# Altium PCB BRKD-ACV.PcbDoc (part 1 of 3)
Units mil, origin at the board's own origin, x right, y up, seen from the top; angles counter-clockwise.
Board outline 5708.66 x 3740.16 mil, 4 copper layers (L1-TOP, L2-GND, L3-PWR, L4-BOT), stack 61.722 mil thick; 171 components, 263 nets, 918 pads, 406 vias.
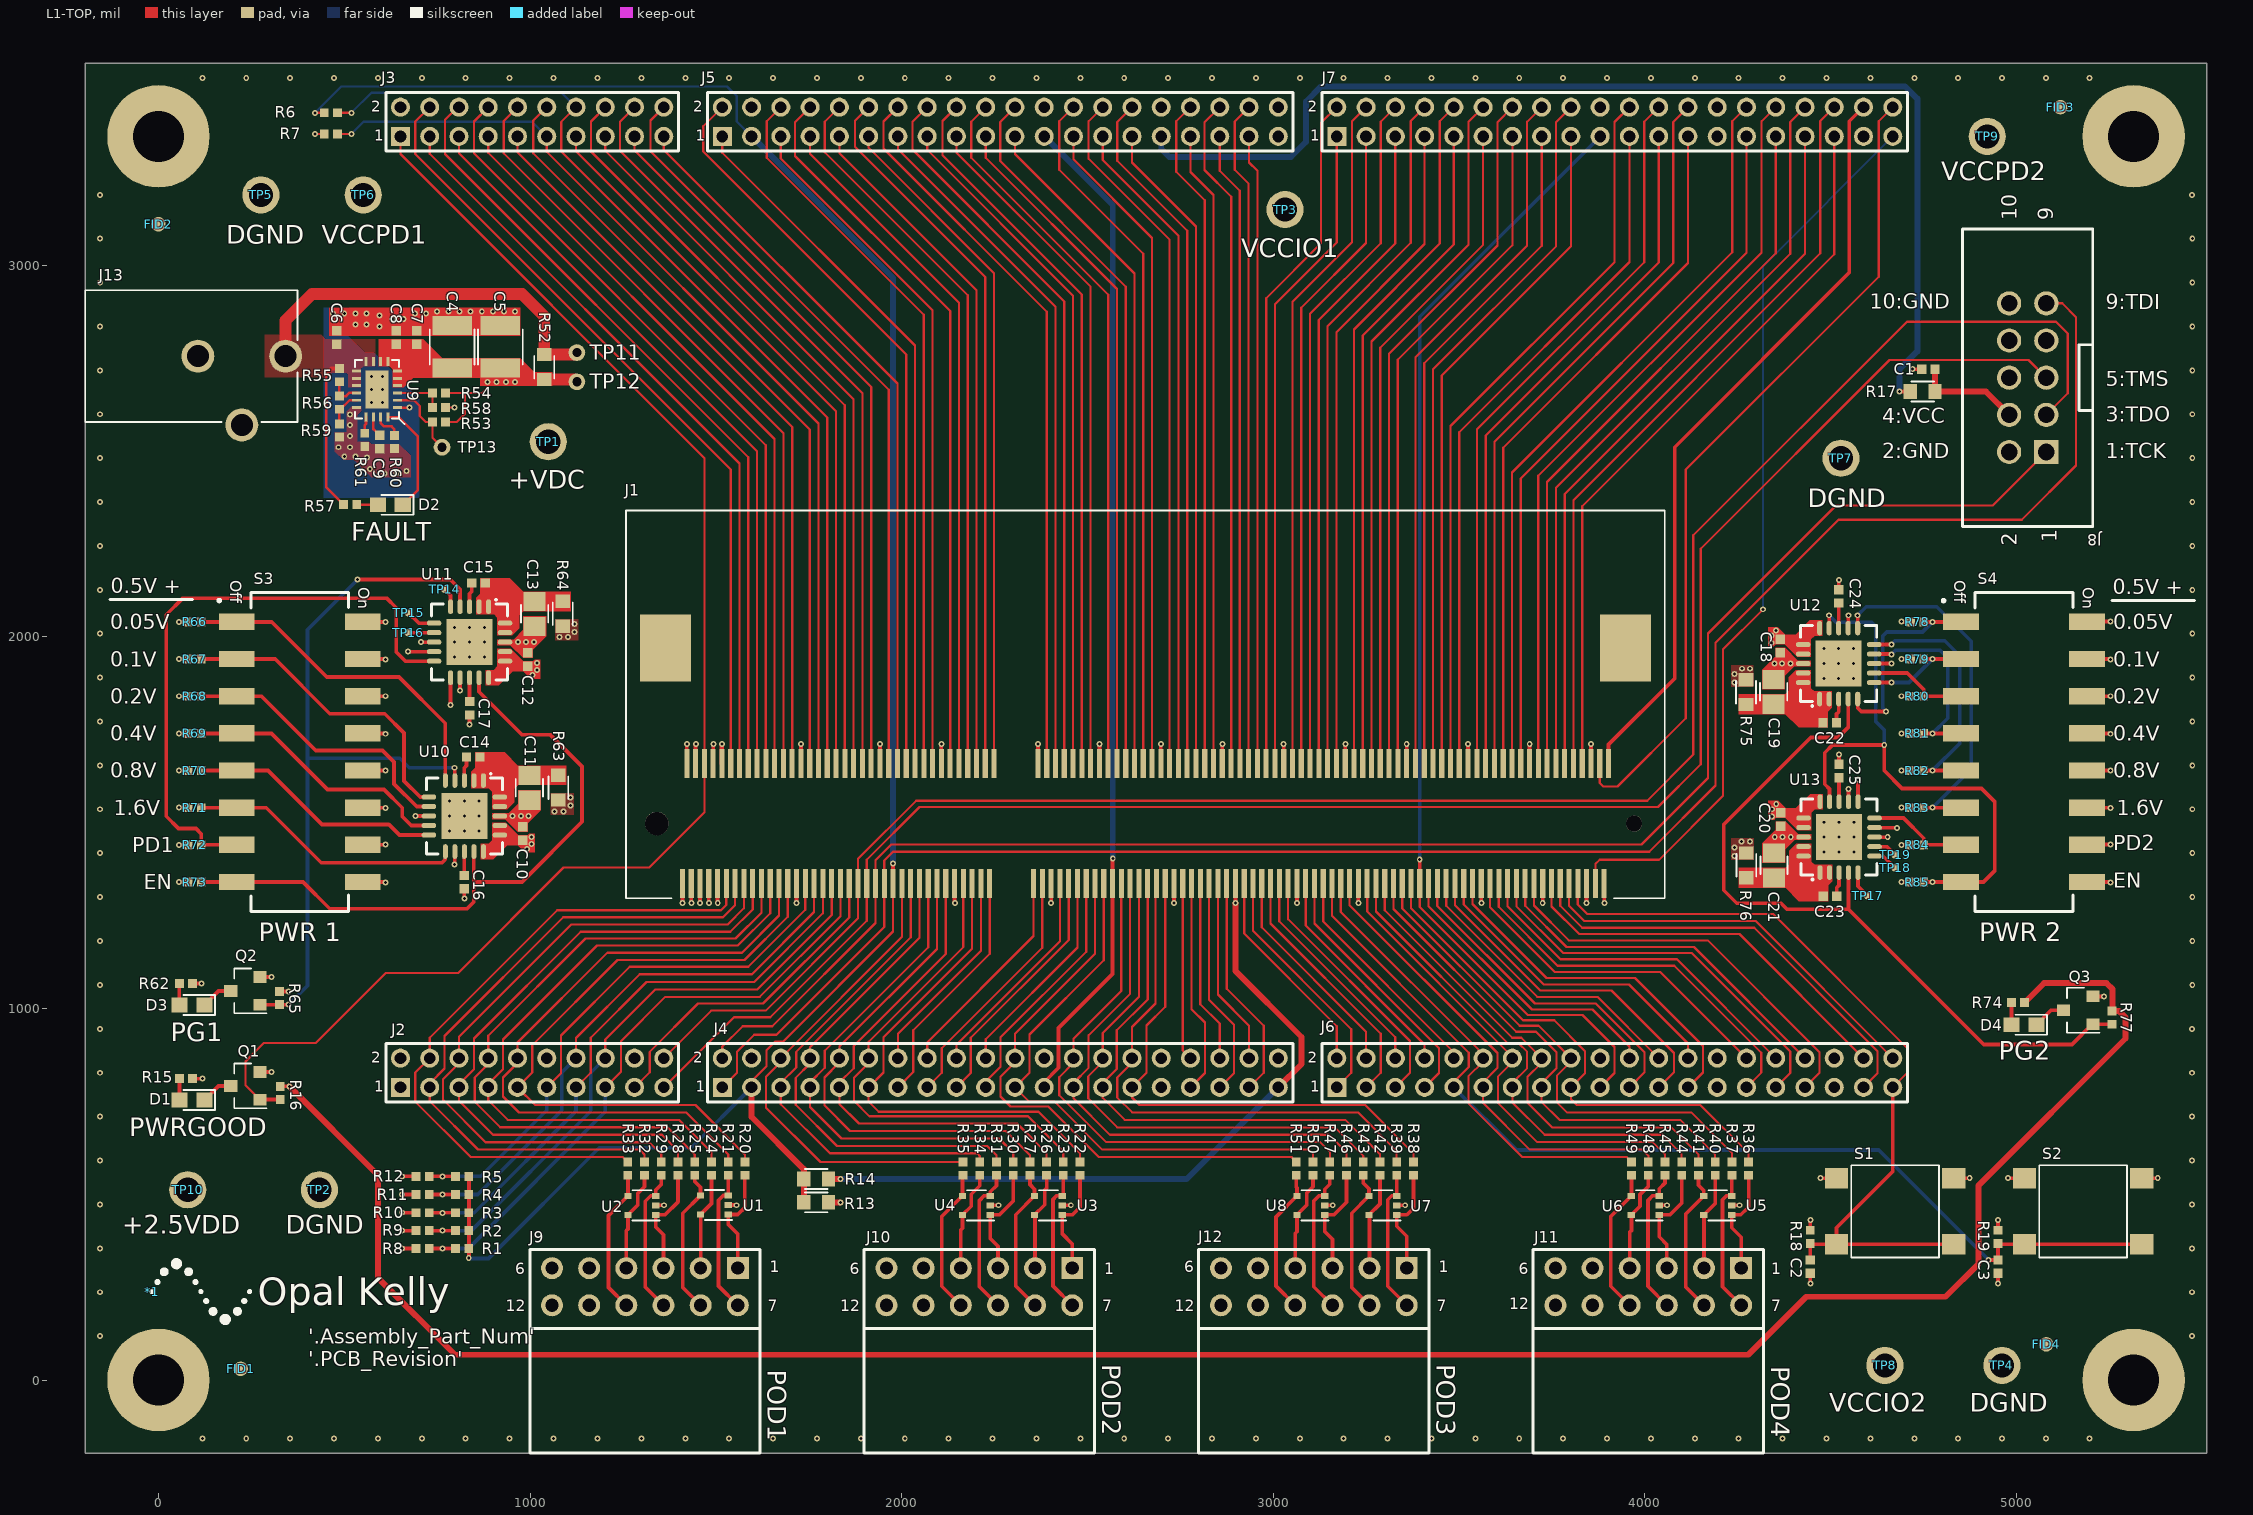
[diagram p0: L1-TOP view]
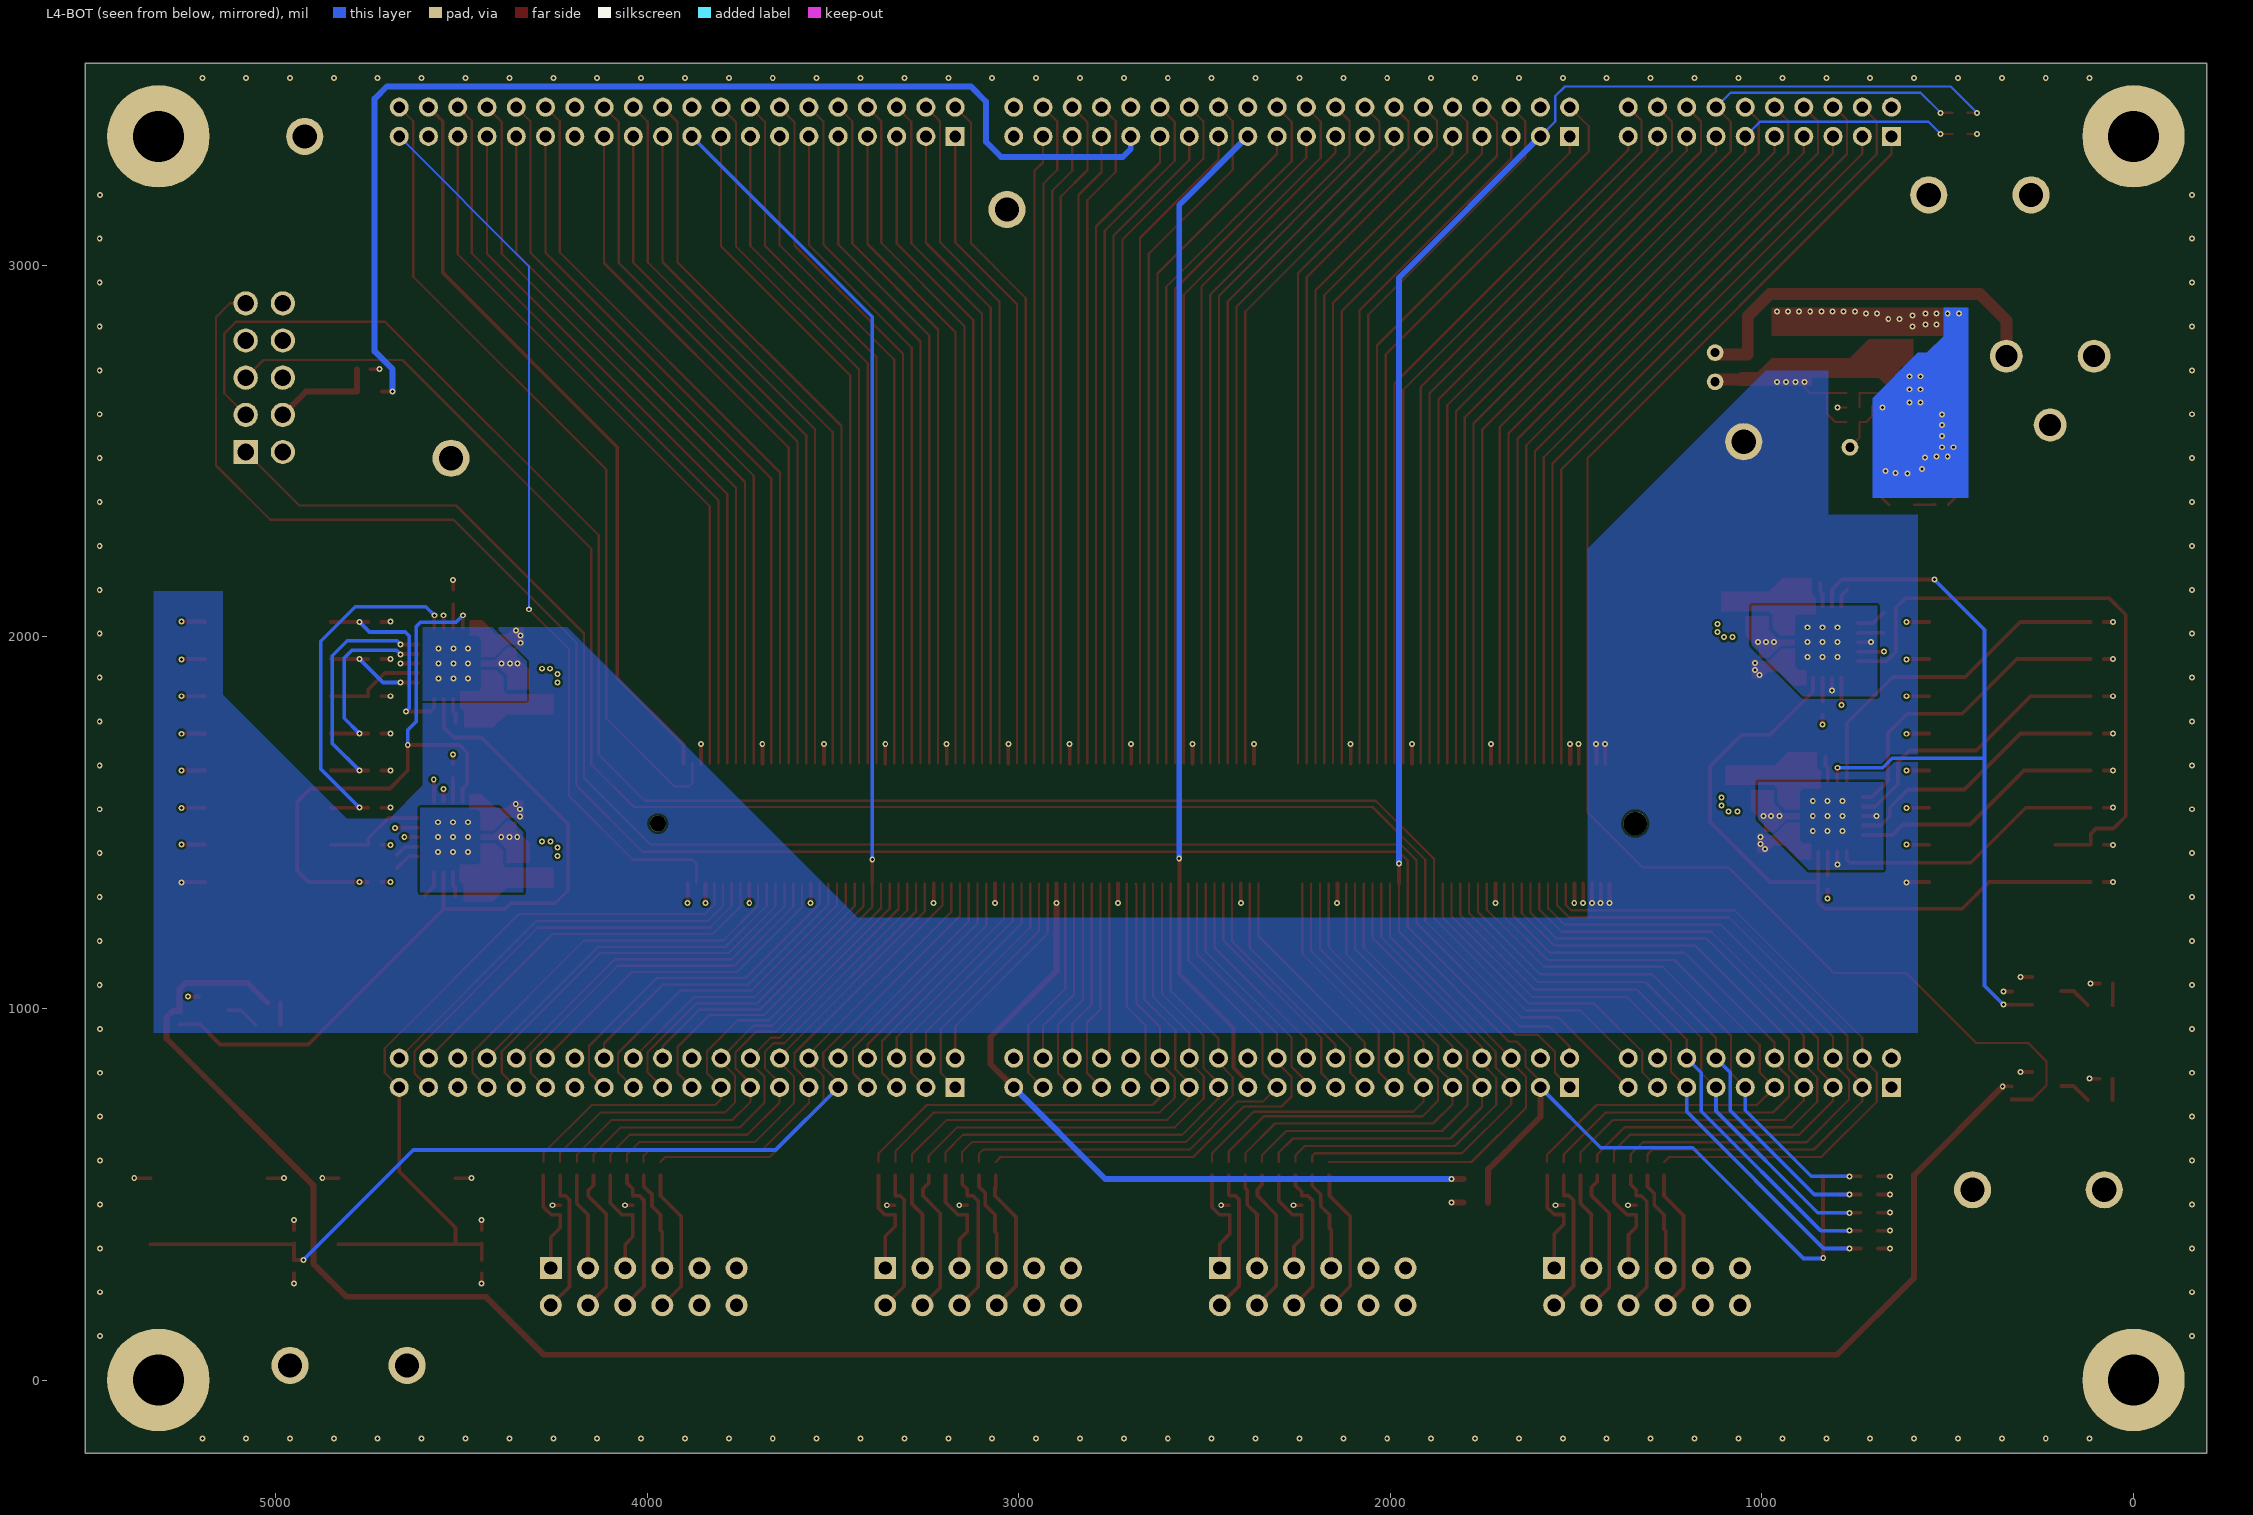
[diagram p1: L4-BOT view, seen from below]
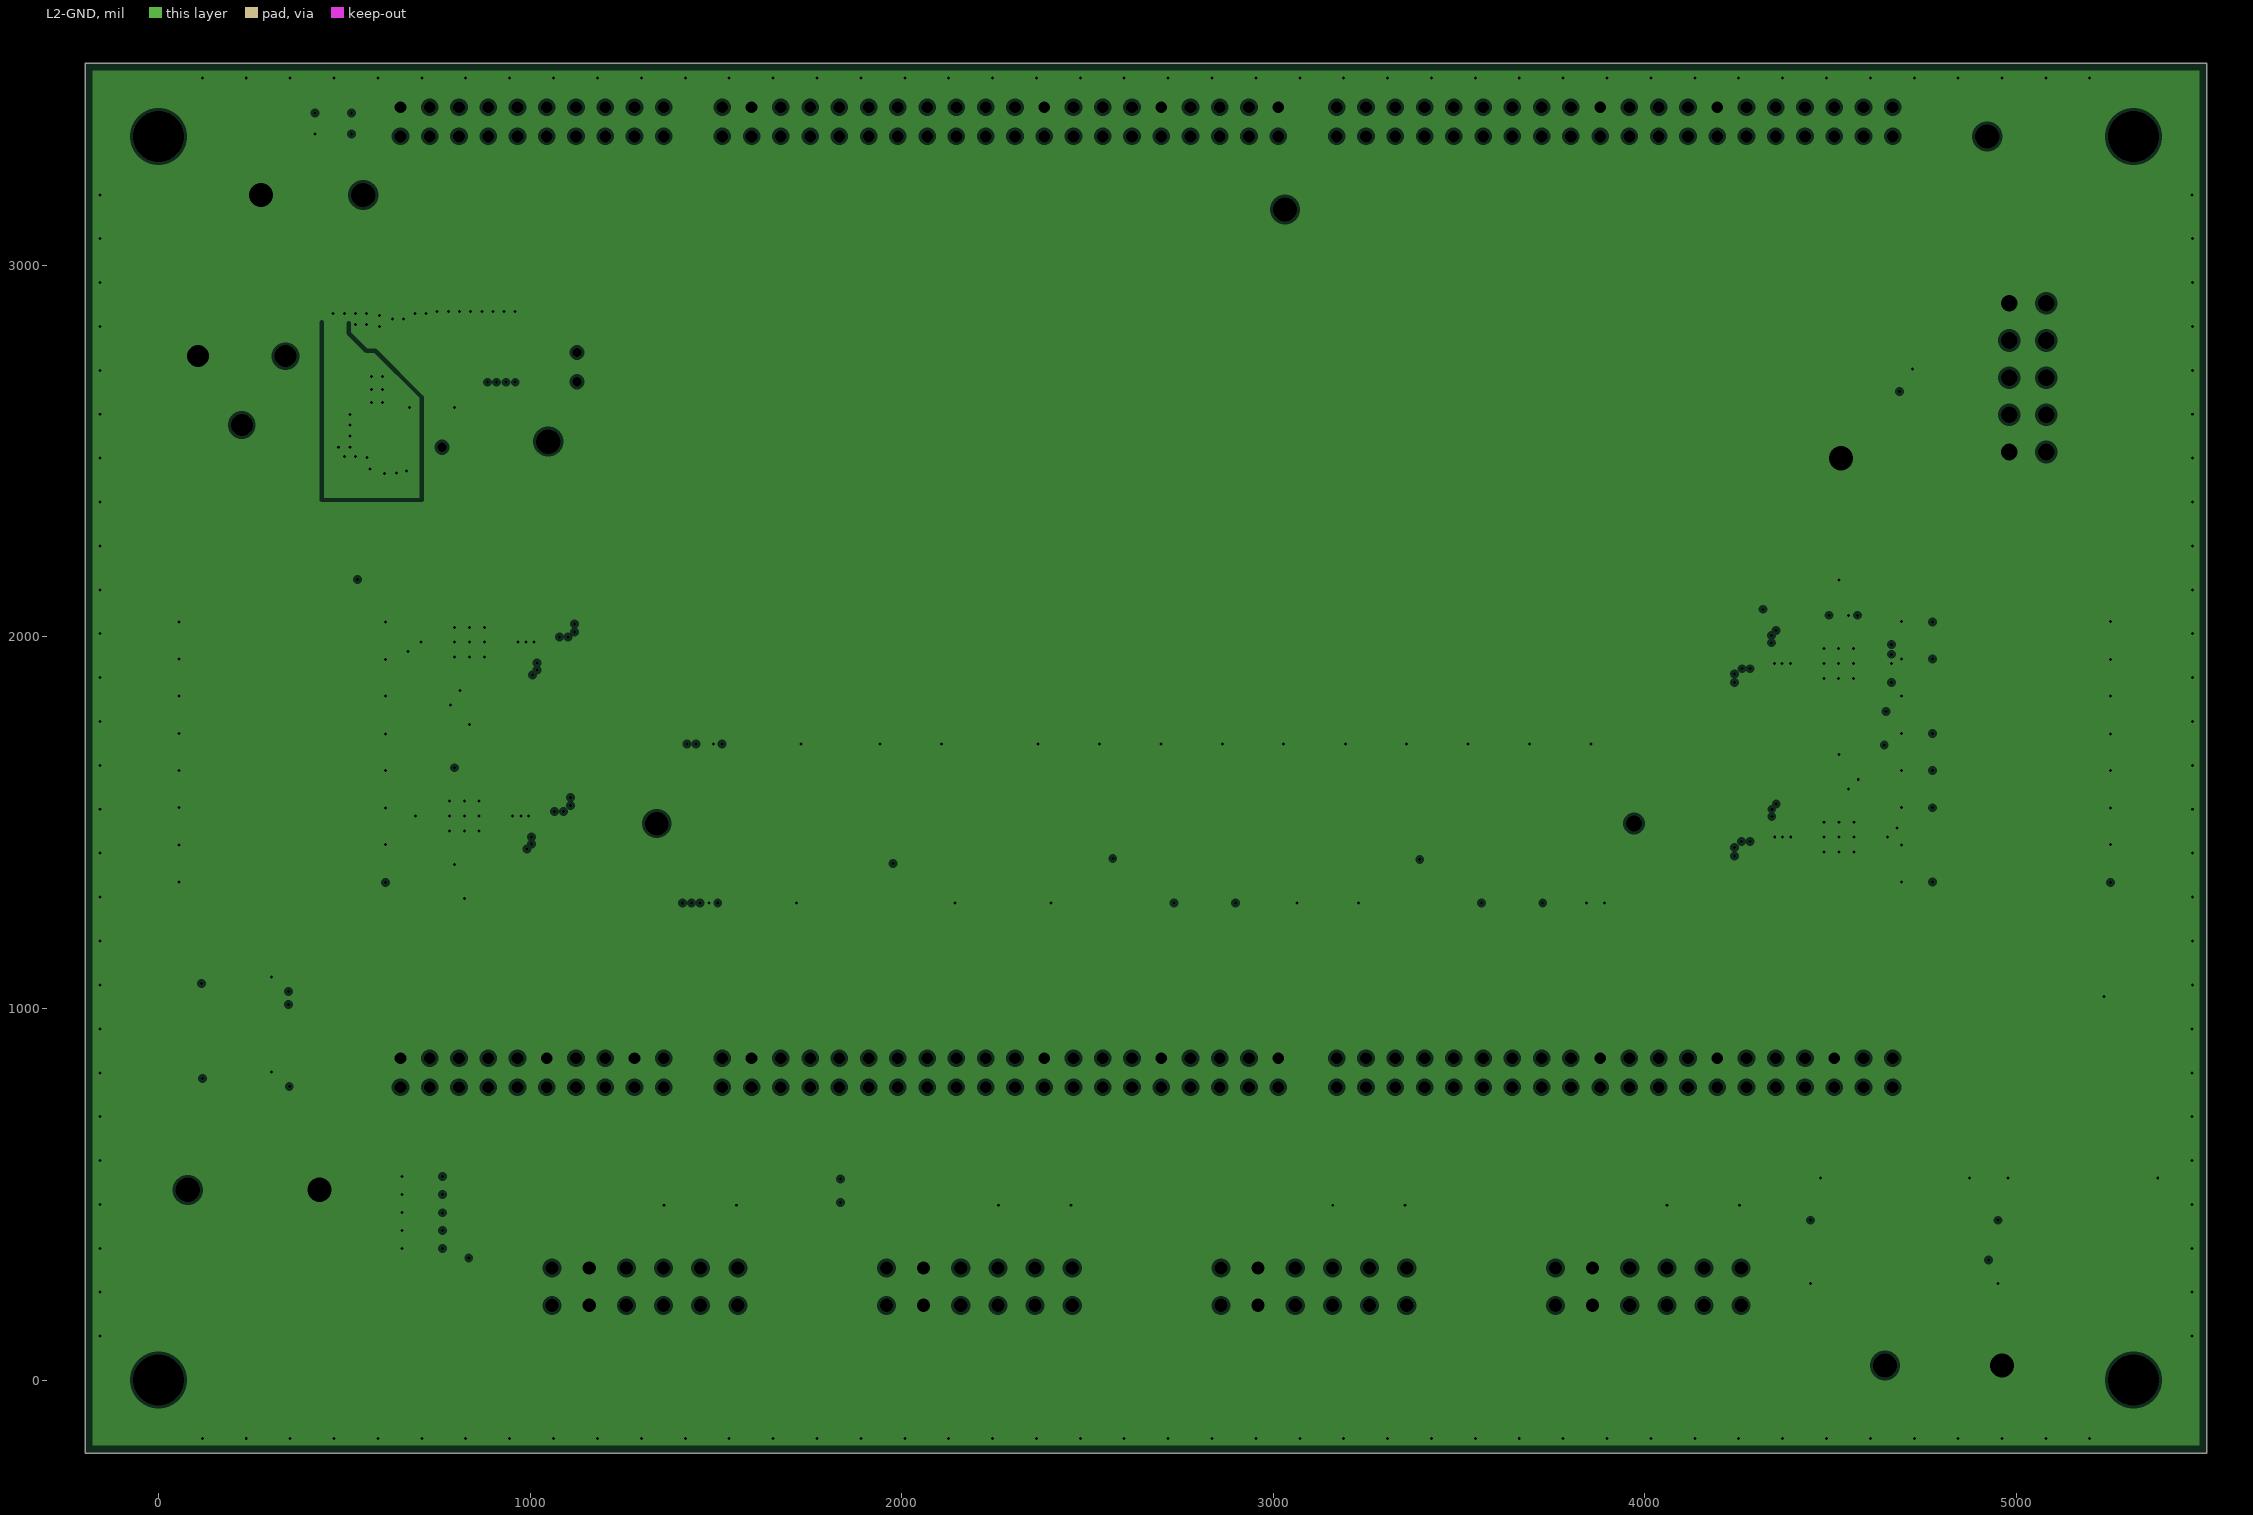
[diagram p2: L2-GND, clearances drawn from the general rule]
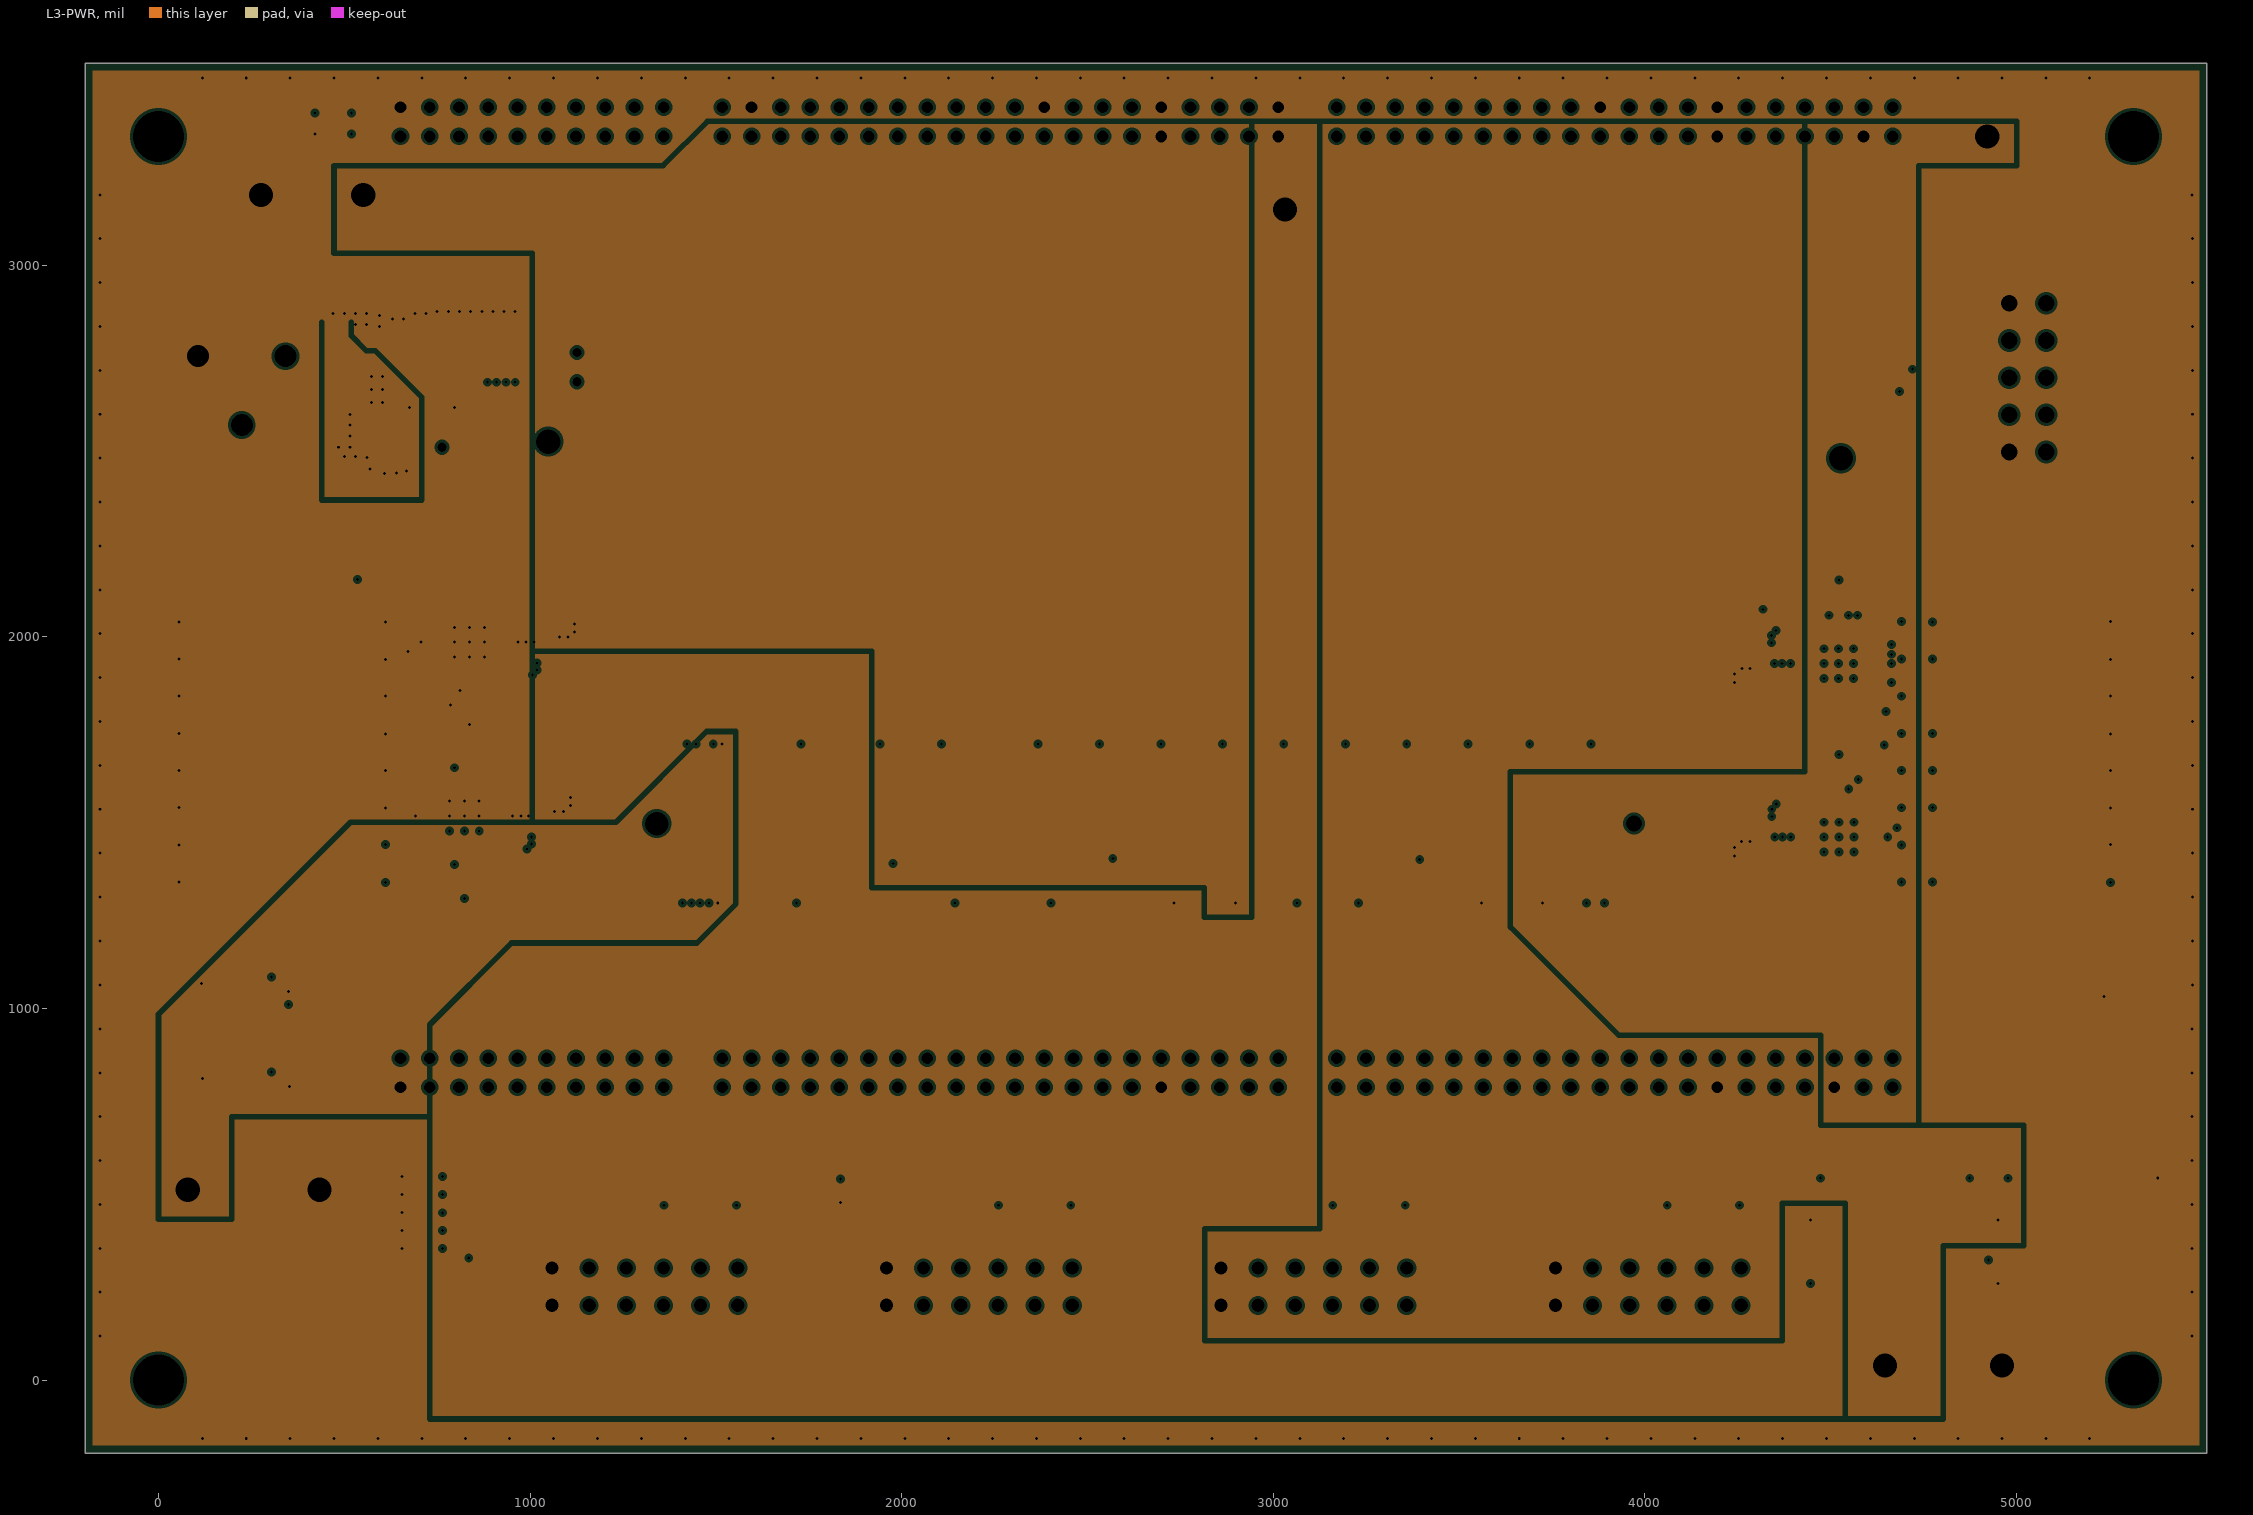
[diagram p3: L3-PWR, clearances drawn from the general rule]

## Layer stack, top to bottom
Top Solder: solder mask 0.4, Solder Resist, Dk 3.5
L1-TOP: signal copper 1.95
Dielectric1: prepreg 2.268, Dk 4.2
Dielectric2: prepreg 2.268, Dk 4.2
L2-GND: plane copper 1.3, net DGND
Dielectric3: core 14, Dk 4.2
Dielectric4: core 6.05, Dk 4.2
Dielectric5: core 6.05, Dk 4.2
Dielectric6: core 6.05, Dk 4.2
Dielectric7: core 14, Dk 4.2
L3-PWR: plane copper 1.3, net (Multiple Nets)
Dielectric8: prepreg 2.268, Dk 4.2
Dielectric9: prepreg 2.268, Dk 4.2
L4-BOT: signal copper 1.95
Bottom Solder: solder mask 0.4, Solder Resist, Dk 3.5

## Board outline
-196.85,-196.85 -196.85,3543.31 5511.81,3543.31 5511.81,-196.85

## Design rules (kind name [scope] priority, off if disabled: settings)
AssemblyTestPointUsage [All] p1 off:
AssemblyTestpoint [All] p1 off: testpointundercomponent=TRUE minsize=40 maxsize=100 preferedsize=60 minholesize=0 maxholesize=40 preferedholesize=32 testpointgrid=1 usegrid=TRUE gridtolerance=0.01 allowsidetop=TRUE allowsidebottom=TRUE
BoardOutlineClearance [All] p1: gap=10 except(0: Arc-SplitContinuation Track-SplitContinuation SMDPad-SplitContinuation THPad-SplitContinuation Via-SplitContinuation Fill-SplitContinuation Poly-SplitContinuation Region-SplitContinuation Text-SplitContinuation)
Clearance okClearanceFiducial [Comment = 'FD0'] p1: gap=100 // Fiducial clearance.
Clearance Clearance_Default [All] p2: gap=6 except(4: Arc-Arc Arc-Track Arc-SMDPad Arc-Via Track-Track Track-SMDPad Track-Via SMDPad-Via THPad-Via Via-Via; 5: Arc-THPad Track-THPad SMDPad-SMDPad SMDPad-THPad THPad-THPad)
ComponentClearance [All] p1 off: gap=10 collisioncheckmode=3 verticalgap=10 showdistances=FALSE
FabricationTestPointUsage TestPointUsage [All] p1 off: valid=0 allowmultiple=FALSE
FabricationTestpoint Testpoint [All] p1: side=3 testpointundercomponent=TRUE minsize=20 maxsize=100 preferedsize=60 minholesize=0 maxholesize=40 preferedholesize=32 testpointgrid=1 allowsidetop=TRUE allowsidebottom=TRUE usegrid=TRUE gridtolerance=0.5
FanoutControl Fanout_Default [All] p1 off: bgadir=Out bgaviamode=Centered fanoutstyle=Auto fanoutdirection=Alternating viagrid=1 // Fanout_Default (Default Rule)
HoleSize [All] p1: absolutevalues=TRUE maxlimit=150 minlimit=8 maxpercent=80.000 minpercent=20.000
LayerPairs [All] p1 off: enforce=TRUE
MinimumSolderMaskSliver [All] p1: minsoldermaskwidth=2.5
PlaneClearance [All] p1: clearance=8
PlaneConnect PlaneConnectNotVia [Not IsVia] p1: planeconnectstyle=Direct reliefexpansion=20 reliefentries=2 reliefconductorwidth=15 reliefairgap=10
PlaneConnect PlaneConnectVia [IsVia] p2: planeconnectstyle=Direct reliefexpansion=20 reliefentries=4 reliefconductorwidth=10 reliefairgap=10
PolygonConnect okxPolyConnectVtt [All vs InPolygon] p1: connectstyle=Direct reliefconductorwidth=10 reliefentries=4 polygonreliefangle="90 Angle" airgapwidth=10 // Enforce dirrect connection to pours for termination.
PolygonConnect [All] p2: connectstyle=Direct reliefconductorwidth=8 reliefentries=4 polygonreliefangle="90 Angle" airgapwidth=10
RoutingCorners [All] p1 off: cornerstyle=45-Degree minsetback=100 maxsetback=100
RoutingLayers [All] p1 off: top layer_v5=TRUE bottom layer_v5=TRUE
RoutingPriority [All] p1 off: routingpriority=0
RoutingTopology [All] p1 off: topology=Shortest
RoutingVias [All] p1: holewidth=8 width=16 viastyle="Through Hole" minholewidth=8 minwidth=16 maxholewidth=10 maxwidth=20
SilkToSilkClearance [All] p1: silktosilkclearance=0.1
SilkToSolderMaskClearance SilkscreenOverComponentPads_OUTLINE [IsPad vs IsTrack] p1: minsilkscreentomaskgap=1 clearancetoexposedcopper=TRUE
SilkToSolderMaskClearance [IsPad] p2: minsilkscreentomaskgap=4 clearancetoexposedcopper=TRUE
SolderMaskExpansion SolderMaskExpansion_U1_U6 [(InComponent('U1')) OR (InComponent('U6'))] p1: expansion=1
SolderMaskExpansion [All] p2: expansion=1
Width [All] p1: maxlimit=50 minlimit=5 preferedwidth=6 minimp=50.000000 maximp=50.000000 favimp=50.000000
9 further rules are at their usual default settings.

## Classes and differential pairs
component class BRKD-ACV-IO-HDR: C1 C2 C3 D1 J1 J2 J3 J4 J5 J6 J7 J8 Q1 R1 R2 R3 R4 R5 R6 R7 R8 R9 R10 R11 R12 R13 R14 R15 R16 R17 R18 R19 S1 S2 TP1 TP2 TP3 TP4 TP5 TP6 TP7 TP8 TP9 TP10
component class BRKD-ACV-IO-PMOD: J9 J10 J11 J12 R20 R21 R22 R23 R24 R25 R26 R27 R28 R29 R30 R31 R32 R33 R34 R35 R36 R37 R38 R39 R40 R41 R42 R43 R44 R45 R46 R47 R48 R49 R50 R51 U1 U2 U3 U4 U5 U6 U7 U8
component class BRKD-ACV-PWR: C4 C5 C6 C7 C8 C9 C10 C11 C12 C13 C14 C15 C16 C17 C18 C19 C20 C21 C22 C23 C24 C25 D2 D3 D4 J13 Q2 Q3 R52 R53 R54 R55 R56 R57 R58 R59 R60 R61 R62 R63 R64 R65 R66 R67 R68 R69 R70 R71 R72 R73 R74 R75 R76 R77 R78 R79 R80 R81 R82 R83 R84 R85 S3 S4 TP11 TP12 TP13 TP14 TP15 TP16 TP17 TP18 TP19 U9 U10 U11 U12 U13
component class Top: *1 FID1 FID2 FID3 FID4

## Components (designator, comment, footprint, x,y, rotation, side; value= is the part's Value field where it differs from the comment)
*1 "Opal Kelly Logo" okLogo-23x5 -17.23,238 r0 top
C1 "C0402C104K8PACTU" CAPC1005X06N 4762.54,2720 r0 top
C2 "C0402C104K8PACTU" CAPC1005X06N 4445,305 r90 top
C3 "C0402C104K8PACTU" CAPC1005X06N 4950,305 r90 top
C4 "GRM32ER61C476KE15K" CAPC3225N 790,2780 r90 top
C5 "GRM32ER61C476KE15K" CAPC3225N 920,2780 r90 top
C6 "C0402C104K8PACTU" CAPC1005X06N 480,2805 r270 top
C7 "C0402C104K8PACTU" CAPC1005X06N 695,2805 r270 top
C8 "LMK105BJ105KV-F" CAPC1005X06N 640,2805 r270 top
C9 "C0402C104K8PACTU" CAPC1005X06N 595,2524 r90 top
C10 "LMK105BJ105KV-F" CAPC1005X06N 980.18,1470.57 r270 top
C11 "LMK212BJ106KG-T" CAPC2012N 998.18,1593.57 r90 top
C12 "LMK105BJ105KV-F" CAPC1005X06N 994.18,1938.57 r270 top
C13 "LMK212BJ106KG-T" CAPC2012N 1012.18,2061.57 r90 top
C14 "C0402C221J5GACTU" CAPC1005X06N 847.18,1676.57 r0 top
C15 "C0402C221J5GACTU" CAPC1005X06N 861.18,2144.57 r0 top
C16 "C0402C103K4RACTU" CAPC1005X06N 823.18,1339.57 r90 top
C17 "C0402C103K4RACTU" CAPC1005X06N 837.18,1807.57 r90 top
C18 "LMK105BJ105KV-F" CAPC1005X06N 4364.36,1974.87 r90 top
C19 "LMK212BJ106KG-T" CAPC2012N 4346.36,1851.87 r270 top
C20 "LMK105BJ105KV-F" CAPC1005X06N 4365.36,1507.87 r90 top
C21 "LMK212BJ106KG-T" CAPC2012N 4347.36,1384.87 r270 top
C22 "C0402C221J5GACTU" CAPC1005X06N 4497.36,1768.87 r180 top
C23 "C0402C221J5GACTU" CAPC1005X06N 4498.36,1301.87 r180 top
C24 "C0402C103K4RACTU" CAPC1005X06N 4521.86,2108.87 r270 top
C25 "C0402C103K4RACTU" CAPC1005X06N 4522.36,1638.87 r270 top
D1 "PWRGOOD" CD1608-0603 90,753.37 r0 top
D2 "FAULT" CD1608-0603 624,2355 r0 top
D3 "PG1" CD1608-0603 90,1009 r0 top
D4 "PG2" CD1608-0603 5020,956 r0 top
FID1 "FIDUCIAL" FID1MM/2MM-SS 221,30 r90 top
FID2 "FIDUCIAL" FID1MM/2MM-SS 0,3110.24 r90 top
FID3 "FIDUCIAL" FID1MM/2MM-SS 5118.11,3425.2 r90 top
FID4 "FIDUCIAL" FID1MM/2MM-SS 5080,96 r90 top
J1 "SODIMM 204-pin 0.6mm" 2013289 1341.06,1497.34 r0 top locked
J2 "0877582016" HDR2X10-2MM 1005.51,826.77 r0 top locked
J3 "0877582016" HDR2X10-2MM 1005.51,3385.83 r0 top locked
J4 "0877584016" HDR2X20-2MM 2265.35,826.77 r0 top locked
J5 "0877584016" HDR2X20-2MM 2265.35,3385.83 r0 top locked
J6 "0877584016" HDR2X20-2MM 3918.9,826.77 r0 top locked
J7 "0877584016" HDR2X20-2MM 3918.9,3385.83 r0 top locked
J8 "JTAG" HDR2X5-SHRD 5030,2697.2 r90 top locked
J9 "POD1" HDR2X6_CEN_RA 1559,301 r180 top locked
J10 "POD2" HDR2X6_CEN_RA 2459,301 r180 top locked
J11 "POD4" HDR2X6_CEN_RA 4259,301 r180 top
J12 "POD3" HDR2X6_CEN_RA 3359,301 r180 top
J13 "+5.0 VDC" CUI-PJ102A -197,2755 r270 top
Q1 "MOSFET-N" SOT23-95P240X110 234,791.37 r90 top
Q2 "MOSFET-N" SOT23-95P240X110 234,1047 r90 top
Q3 "MOSFET-N" SOT23-95P240X110 5166,995 r90 top
R1 "CRCW04020000Z0ED" RESC1005X06N 817,354 r0 top
R2 "CRCW040210K0JNED" RESC1005X06N 817,402 r0 top
R3 "CRCW040210K0JNED" RESC1005X06N 817,450 r180 top
R4 "CRCW04020000Z0ED" RESC1005X06N 817,499 r0 top
R5 "CRCW040210K0JNED" RESC1005X06N 817,548 r180 top
R6 "CRCW040210K0JNED" RESC1005X06N 464,3410 r180 top
R7 "CRCW04020000Z0ED" RESC1005X06N 464,3353 r0 top
R8 "CRCW040210K0JNED" RESC1005X06N 711,354 r180 top
R9 "CRCW04020000Z0ED" RESC1005X06N 711,402 r0 top
R10 "CRCW04020000Z0ED" RESC1005X06N 711,450 r0 top
R11 "CRCW040210K0JNED" RESC1005X06N 711,499 r180 top
R12 "CRCW04020000Z0ED" RESC1005X06N 711,548 r0 top
R13 "CRCW06030000Z0EA" RESC1608N 1770,478 r180 top
R14 "CRCW06030000Z0EA" RESC1608N 1770,541 r180 top
R15 "CRCW0402100RFKED" RESC1005X06N 74,811 r0 top
R16 "CRCW040210K0JNED" RESC1005X06N 328,772.37 r90 top
R17 "CRCW06030000Z0EA" RESC1608N 4747.54,2660 r180 top
R18 "CRCW040210K0JNED" RESC1005X06N 4445,385 r90 top
R19 "CRCW040210K0JNED" RESC1005X06N 4950,385 r90 top
R20 "CRCW0402200RFKED" RESC1005X06N 1578,569 r270 top
R21 "CRCW0402200RFKED" RESC1005X06N 1533,569 r270 top
R22 "CRCW0402200RFKED" RESC1005X06N 2480,569 r270 top
R23 "CRCW0402200RFKED" RESC1005X06N 2435,569 r270 top
R24 "CRCW0402200RFKED" RESC1005X06N 1488,569 r270 top
R25 "CRCW0402200RFKED" RESC1005X06N 1443,569 r270 top
R26 "CRCW0402200RFKED" RESC1005X06N 2390,569 r270 top
R27 "CRCW0402200RFKED" RESC1005X06N 2345,569 r270 top
R28 "CRCW0402200RFKED" RESC1005X06N 1398,569 r270 top
R29 "CRCW0402200RFKED" RESC1005X06N 1353,569 r270 top
R30 "CRCW0402200RFKED" RESC1005X06N 2300,569 r270 top
R31 "CRCW0402200RFKED" RESC1005X06N 2255,569 r270 top
R32 "CRCW0402200RFKED" RESC1005X06N 1308,569 r270 top
R33 "CRCW0402200RFKED" RESC1005X06N 1263,569 r270 top
R34 "CRCW0402200RFKED" RESC1005X06N 2210,569 r270 top
R35 "CRCW0402200RFKED" RESC1005X06N 2165,569 r270 top
R36 "CRCW0402200RFKED" RESC1005X06N 4279,569 r270 top
R37 "CRCW0402200RFKED" RESC1005X06N 4234,569 r270 top
R38 "CRCW0402200RFKED" RESC1005X06N 3377,569 r270 top
R39 "CRCW0402200RFKED" RESC1005X06N 3332,569 r270 top
R40 "CRCW0402200RFKED" RESC1005X06N 4189,569 r270 top
R41 "CRCW0402200RFKED" RESC1005X06N 4144,569 r270 top
R42 "CRCW0402200RFKED" RESC1005X06N 3287,569 r270 top
R43 "CRCW0402200RFKED" RESC1005X06N 3242,569 r270 top
R44 "CRCW0402200RFKED" RESC1005X06N 4099,569 r270 top
R45 "CRCW0402200RFKED" RESC1005X06N 4054,569 r270 top
R46 "CRCW0402200RFKED" RESC1005X06N 3197,569 r270 top
R47 "CRCW0402200RFKED" RESC1005X06N 3152,569 r270 top
R48 "CRCW0402200RFKED" RESC1005X06N 4009,569 r270 top
R49 "CRCW0402200RFKED" RESC1005X06N 3964,569 r270 top
R50 "CRCW0402200RFKED" RESC1005X06N 3107,569 r270 top
R51 "CRCW0402200RFKED" RESC1005X06N 3062,569 r270 top
R52 "CRCW06030000Z0EA" RESC1608N 1038,2726 r270 top
R53 "CRCW040210K0JNED" RESC1005X06N 755,2578 r0 top
R54 "CRCW040216K9FKED" RESC1005X06N 755,2656 r0 top
R55 "CRCW0402100KFKED" RESC1005X06N 487,2704 r90 top
R56 "CRCW040224K9FKED" RESC1005X06N 487,2630 r90 top
R57 "CRCW0402330RJNED" RESC1005X06N 516,2356 r180 top
R58 "CRCW04024K75FKED" RESC1005X06N 755,2617 r180 top
R59 "CRCW040227K4FKED" RESC1005X06N 487,2555 r90 top
R60 "CRCW040224K9FKED" RESC1005X06N 635,2524 r90 top
R61 "CRCW040216K9FKED" RESC1005X06N 555,2530 r90 top
R62 "CRCW0402100RFKED" RESC1005X06N 74,1067 r0 top
R63 "CRCW06030000Z0EA" RESC1608N 1076,1594 r270 top
R64 "CRCW06030000Z0EA" RESC1608N 1088,2062 r270 top
R65 "CRCW040210K0JNED" RESC1005X06N 326,1028 r90 top
R66 "CRCW040210K0JNED" RESC1005X06N 97.72,2040 r0 top
R67 "CRCW040210K0JNED" RESC1005X06N 97.72,1940 r0 top
R68 "CRCW040210K0JNED" RESC1005X06N 97.72,1840 r0 top
R69 "CRCW040210K0JNED" RESC1005X06N 97.72,1740 r0 top
R70 "CRCW040210K0JNED" RESC1005X06N 97.72,1640 r0 top
R71 "CRCW040210K0JNED" RESC1005X06N 97.72,1540 r0 top
R72 "CRCW040210K0JNED" RESC1005X06N 97.72,1440 r0 top
R73 "CRCW040210K0JNED" RESC1005X06N 97.72,1340 r0 top
R74 "CRCW0402100RFKED" RESC1005X06N 5004,1016 r0 top
R75 "CRCW06030000Z0EA" RESC1608N 4272,1851 r90 top
R76 "CRCW06030000Z0EA" RESC1608N 4273,1385 r90 top
R77 "CRCW040210K0JNED" RESC1005X06N 5257,975 r90 top
R78 "CRCW040210K0JNED" RESC1005X06N 4732.28,2040 r0 top
R79 "CRCW040210K0JNED" RESC1005X06N 4732.28,1940 r0 top
R80 "CRCW040210K0JNED" RESC1005X06N 4732.28,1840 r0 top
R81 "CRCW040210K0JNED" RESC1005X06N 4732.28,1740 r0 top
R82 "CRCW040210K0JNED" RESC1005X06N 4732.28,1640 r0 top
R83 "CRCW040210K0JNED" RESC1005X06N 4732.28,1540 r0 top
R84 "CRCW040210K0JNED" RESC1005X06N 4732.28,1440 r0 top
R85 "CRCW040210K0JNED" RESC1005X06N 4732.28,1340 r0 top
S1 "SW-PB" SW_BFS 4673,454 r0 top
S2 "SW-PB" SW_BFS 5179,454 r0 top
S3 "Dip Switch SPST" 219-8XXST 380,1690 r270 top
S4 "Dip Switch SPST" 219-8XXST 5020,1690 r270 top
TP1 "+VDC" TP_MED 1049,2525 r90 top
TP2 "DGND" TP_MED 433.07,511.81 r90 top
TP3 "VCCIO1" TP_MED 3031.5,3149.61 r90 top
TP4 "DGND" TP_MED 4960.63,39.37 r90 top
TP5 "DGND" TP_MED 275.59,3188.98 r90 top
TP6 "VCCPD1" TP_MED 551.18,3188.98 r90 top
TP7 "DGND" TP_MED 4527.56,2480.31 r90 top
TP8 "VCCIO2" TP_MED 4645.67,39.37 r90 top
TP9 "VCCPD2" TP_MED 4921.26,3346.46 r90 top
TP10 "+2.5VDD" TP_MED 78.74,511.81 r90 top
TP11 "TP-PTH-25/45" TP-PTH-25/45 1126,2764.74 r90 top
TP12 "TP-PTH-25/45" TP-PTH-25/45 1126,2686 r90 top
TP13 "TP-PTH-25/45" TP-PTH-25/45 763,2510 r180 top
TP14 "TESTPOINT-SMD20" TP-SMD20 770,2128 r90 top
TP15 "TESTPOINT-SMD20" TP-SMD20 673,2064 r90 top
TP16 "TESTPOINT-SMD20" TP-SMD20 672,2011 r90 top
TP17 "TESTPOINT-SMD20" TP-SMD20 4599,1303 r90 top
TP18 "TESTPOINT-SMD20" TP-SMD20 4673,1378 r90 top
TP19 "TESTPOINT-SMD20" TP-SMD20 4673,1413 r90 top
U1 "NSQA6V8AW5T2G" SOT-323-5 1496,471 r90 top
U2 "NSQA6V8AW5T2G" SOT-323-5 1301,470 r90 top
U3 "NSQA6V8AW5T2G" SOT-323-5 2395,470 r90 top
U4 "NSQA6V8AW5T2G" SOT-323-5 2201,470 r90 top
U5 "NSQA6V8AW5T2G" SOT-323-5 4196,470 r90 top
U6 "NSQA6V8AW5T2G" SOT-323-5 4001,470 r90 top
U7 "NSQA6V8AW5T2G" SOT-323-5 3295,470 r90 top
U8 "NSQA6V8AW5T2G" SOT-323-5 3101,470 r90 top
U9 "TPS25940A" TPS25940 588,2666 r90 top
U10 "TPS7A7100RGWT" S-PVQN-N20 823.18,1517.57 r270 top
U11 "TPS7A7100RGWT" S-PVQN-N20 837.18,1985.57 r270 top
U12 "TPS7A7100RGWT" S-PVQN-N20 4521.36,1927.87 r90 top
U13 "TPS7A7100RGWT" S-PVQN-N20 4522.36,1460.87 r90 top

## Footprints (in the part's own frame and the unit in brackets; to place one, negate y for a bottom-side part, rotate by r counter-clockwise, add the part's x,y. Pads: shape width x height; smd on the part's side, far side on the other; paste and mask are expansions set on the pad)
219-8XXST [mil] "16 pin SMT Dip Switch, 8 SPST"
  rect 44x96 smd: 1(-350,-169.5) 2(-250,-169.5) 3(-150,-169.5) 4(-50,-169.5) 5(50,-169.5) 6(150,-169.5) 7(250,-169.5) 8(350,-169.5) 9(350,169.5) 10(250,169.5) 11(150,169.5) 12(50,169.5) 13(-50,169.5) 14(-150,169.5) 15(-250,169.5) 16(-350,169.5)
  silkscreen extent -429,-220 429,132
2013289 [mm] "SODIMM socket, DDR3, 204-pin"
  rect 0.35x2 smd mask+0.3: 1(1.75,-4.1) 2(2.05,4.1) 3(2.35,-4.1) 4(2.65,4.1) 5(2.95,-4.1) 6(3.25,4.1) 7(3.55,-4.1) 8(3.85,4.1) 9(4.15,-4.1) 10(4.45,4.1) 11(4.75,-4.1) 12(5.05,4.1) 13(5.35,-4.1) 14(5.65,4.1) 15(5.95,-4.1) 16(6.25,4.1) 17(6.55,-4.1) 18(6.85,4.1) 19(7.15,-4.1) 20(7.45,4.1) 21(7.75,-4.1) 22(8.05,4.1) 23(8.35,-4.1) 24(8.65,4.1) 25(8.95,-4.1) 26(9.25,4.1) 27(9.55,-4.1) 28(9.85,4.1) 29(10.15,-4.1) 30(10.45,4.1) 31(10.75,-4.1) 32(11.05,4.1) 33(11.35,-4.1) 34(11.65,4.1) 35(11.95,-4.1) 36(12.25,4.1) 37(12.55,-4.1) 38(12.85,4.1) 39(13.15,-4.1) 40(13.45,4.1) 41(13.75,-4.1) 42(14.05,4.1) 43(14.35,-4.1) 44(14.65,4.1) 45(14.95,-4.1) 46(15.25,4.1) 47(15.55,-4.1) 48(15.85,4.1) 49(16.15,-4.1) 50(16.45,4.1) 51(16.75,-4.1) 52(17.05,4.1) 53(17.35,-4.1) 54(17.65,4.1) 55(17.95,-4.1) 56(18.25,4.1) 57(18.55,-4.1) 58(18.85,4.1) 59(19.15,-4.1) 60(19.45,4.1) 61(19.75,-4.1) 62(20.05,4.1) 63(20.35,-4.1) 64(20.65,4.1) 65(20.95,-4.1) 66(21.25,4.1) 67(21.55,-4.1) 68(21.85,4.1) 69(22.15,-4.1) 70(22.45,4.1) 71(22.75,-4.1) 72(23.05,4.1) 73(25.75,-4.1) 74(26.05,4.1) 75(26.35,-4.1) 76(26.65,4.1) 77(26.95,-4.1) 78(27.25,4.1) 79(27.55,-4.1) 80(27.85,4.1) 81(28.15,-4.1) 82(28.45,4.1) 83(28.75,-4.1) 84(29.05,4.1) 85(29.35,-4.1) 86(29.65,4.1) 87(29.95,-4.1) 88(30.25,4.1) 89(30.55,-4.1) 90(30.85,4.1) 91(31.15,-4.1) 92(31.45,4.1) 93(31.75,-4.1) 94(32.05,4.1) 95(32.35,-4.1) 96(32.65,4.1) 97(32.95,-4.1) 98(33.25,4.1) 99(33.55,-4.1) 100(33.85,4.1) 101(34.15,-4.1) 102(34.45,4.1) 103(34.75,-4.1) 104(35.05,4.1) 105(35.35,-4.1) 106(35.65,4.1) 107(35.95,-4.1) 108(36.25,4.1) 109(36.55,-4.1) 110(36.85,4.1) 111(37.15,-4.1) 112(37.45,4.1) 113(37.75,-4.1) 114(38.05,4.1) 115(38.35,-4.1) 116(38.65,4.1) 117(38.95,-4.1) 118(39.25,4.1) 119(39.55,-4.1) 120(39.85,4.1) 121(40.15,-4.1) 122(40.45,4.1) 123(40.75,-4.1) 124(41.05,4.1) 125(41.35,-4.1) 126(41.65,4.1) 127(41.95,-4.1) 128(42.25,4.1) 129(42.55,-4.1) 130(42.85,4.1) 131(43.15,-4.1) 132(43.45,4.1) 133(43.75,-4.1) 134(44.05,4.1) 135(44.35,-4.1) 136(44.65,4.1) 137(44.95,-4.1) 138(45.25,4.1) 139(45.55,-4.1) 140(45.85,4.1) 141(46.15,-4.1) 142(46.45,4.1) 143(46.75,-4.1) 144(47.05,4.1) 145(47.35,-4.1) 146(47.65,4.1) 147(47.95,-4.1) 148(48.25,4.1) 149(48.55,-4.1) 150(48.85,4.1) 151(49.15,-4.1) 152(49.45,4.1) 153(49.75,-4.1) 154(50.05,4.1) 155(50.35,-4.1) 156(50.65,4.1) 157(50.95,-4.1) 158(51.25,4.1) 159(51.55,-4.1) 160(51.85,4.1) 161(52.15,-4.1) 162(52.45,4.1) 163(52.75,-4.1) 164(53.05,4.1) 165(53.35,-4.1) 166(53.65,4.1) 167(53.95,-4.1) 168(54.25,4.1) 169(54.55,-4.1) 170(54.85,4.1) 171(55.15,-4.1) 172(55.45,4.1) 173(55.75,-4.1) 174(56.05,4.1) 175(56.35,-4.1) 176(56.65,4.1) 177(56.95,-4.1) 178(57.25,4.1) 179(57.55,-4.1) 180(57.85,4.1) 181(58.15,-4.1) 182(58.45,4.1) 183(58.75,-4.1) 184(59.05,4.1) 185(59.35,-4.1) 186(59.65,4.1) 187(59.95,-4.1) 188(60.25,4.1) 189(60.55,-4.1) 190(60.85,4.1) 191(61.15,-4.1) 192(61.45,4.1) 193(61.75,-4.1) 194(62.05,4.1) 195(62.35,-4.1) 196(62.65,4.1) 197(62.95,-4.1) 198(63.25,4.1) 199(63.55,-4.1) 200(63.85,4.1) 201(64.15,-4.1) 202(64.45,4.1) 203(64.75,-4.1) 204(65.05,4.1)
  round 1.6 hole 1.6 unplated paste+0: MH(0,0)
  round 1.1 hole 1.1 unplated paste+0: MH(66.8,0)
  rect 3.5x4.6 smd mask+0.3: MTG(0.6,12) MTG(66.2,12)
  silkscreen extent -2.1,-5.1 68.9,21.4
CAPC1005X06N [mm] "Chip Capacitor, 2-Leads, Body 1.00x0.50mm, IPC Medium Density"
  rect 0.64x0.64 smd: 1(-0.46,0) 2(0.46,0)
  body extent -0.55,-0.3 0.55,0.3, height 0.6
CAPC2012N [mm] "Chip Capacitor, Body 2.0x1.3mm, IPC Medium Density"
  rect 1.3x1.5 smd: 1(-0.85,0) 2(0.85,0)
  silkscreen extent -0.6,-0.93 0.6,0.93, body extent -1.1,-0.72 1.1,0.72, height 1.1
CAPC3225N [mm] "Chip Capacitor, Body 3.2x2.5mm, IPC Medium Density"
  rect 1.3x2.7 smd: 1(-1.45,0) 2(1.45,0)
  silkscreen extent -1.2,-1.53 1.2,1.53, body extent -1.7,-1.35 1.7,1.35, height 1.35
CD1608-0603 [mm] "Chip Diode; Body 1.6 x 0.8 mm (LxW typ)"
  rect 1.1x1 smd: 1(-0.85,0) 2(0.85,0)
  silkscreen extent -0.6,-0.68 1.58,0.68
CUI-PJ102A [mm] "2.1mm/5.5mm DC power jack"
  round 2.25 hole 1.5: 1(0,13.7) 2(0,7.7) 3(4.7,10.7)
  silkscreen extent -4.5,0 4.5,14.5
FID1MM/2MM-SS [mm] "Fiducial 1mm copper, 2mm soldermask, single-side"
  round 1 smd paste-0.5 mask+0.5: FID?(0,0)
HDR2X5-SHRD [mil] "0.1\" 2x5 shrouded header"
  rect 65x65 hole 44.88: 1(-200,-50)
  round 65 hole 44.88: 2(-200,50) 3(-100,-50) 4(-100,50) 5(0,-50) 6(0,50) 7(100,-50) 8(100,50) 9(200,-50) 10(200,50)
  silkscreen extent -400,-175 400,175
HDR2X6_CEN_RA [mm] "2mm 2x20 header"
  rect 1.5x1.5 hole 0.9: 1(0,0)
  round 1.5 hole 0.9: 2(2.54,0) 3(5.08,0) 4(7.62,0) 5(10.16,0) 6(12.7,0) 7(0,2.54) 8(2.54,2.54) 9(5.08,2.54) 10(7.62,2.54) 11(10.16,2.54) 12(12.7,2.54)
  silkscreen extent -1.52,-1.27 14.22,12.64
HDR2X10-2MM [mm] "2mm 2x10 header"
  rect 1.3x1.3 hole 0.8: 1(-9,-1)
  round 1.3 hole 0.8: 2(-9,1) 3(-7,-1) 4(-7,1) 5(-5,-1) 6(-5,1) 7(-3,-1) 8(-3,1) 9(-1,-1) 10(-1,1) 11(1,-1) 12(1,1) 13(3,-1) 14(3,1) 15(5,-1) 16(5,1) 17(7,-1) 18(7,1) 19(9,-1) 20(9,1)
  silkscreen extent -10,-2 10,2
HDR2X20-2MM [mm] "2mm 2x20 header"
  rect 1.3x1.3 hole 0.8: 1(-19,-1)
  round 1.3 hole 0.8: 2(-19,1) 3(-17,-1) 4(-17,1) 5(-15,-1) 6(-15,1) 7(-13,-1) 8(-13,1) 9(-11,-1) 10(-11,1) 11(-9,-1) 12(-9,1) 13(-7,-1) 14(-7,1) 15(-5,-1) 16(-5,1) 17(-3,-1) 18(-3,1) 19(-1,-1) 20(-1,1) 21(1,-1) 22(1,1) 23(3,-1) 24(3,1) 25(5,-1) 26(5,1) 27(7,-1) 28(7,1) 29(9,-1) 30(9,1) 31(11,-1) 32(11,1) 33(13,-1) 34(13,1) 35(15,-1) 36(15,1) 37(17,-1) 38(17,1) 39(19,-1) 40(19,1)
  silkscreen extent -20,-2 20,2
okLogo-23x5 [mil] "Opal Kelly silkscreen logo (23mm x 5mm)"
  silkscreen extent -3,-82 266,82
RESC1005X06N [mm] "Chip Resistor, 2-Leads, Body 1.00x0.50mm, IPC Medium Density"
  rect 0.6x0.6 smd: 1(-0.45,0) 2(0.45,0)
  body extent -0.55,-0.3 0.55,0.3, height 0.6
RESC1608N [mm] "Chip Resistor, Body 1.6x0.8mm, IPC Medium Density"
  rect 0.9x1 smd: 1(-0.85,0) 2(0.85,0)
  silkscreen extent -0.77,-0.68 0.78,0.68, body extent -0.85,-0.48 0.85,0.48, height 0.6
S-PVQN-N20 [mm]
  rect 3.15x3.15 smd paste-4: 0(0,0)
  rrect100% 1x0.35 smd mask+0.07: 1(-2.425,1.3) 2(-2.425,0.65) 3(-2.425,0) 4(-2.425,-0.65) 5(-2.425,-1.3) 11(2.425,-1.3) 12(2.425,-0.65) 13(2.425,0) 14(2.425,0.65) 15(2.425,1.3)
  rrect100% 0.35x1 smd mask+0.07: 6(-1.3,-2.425) 7(-0.65,-2.425) 8(0,-2.425) 9(0.65,-2.425) 10(1.3,-2.425) 16(1.3,2.425) 17(0.65,2.425) 18(0,2.425) 19(-0.65,2.425) 20(-1.3,2.425)
  silkscreen extent -2.9,-2.6 2.6,2.6
SOT23-95P240X110 [mm] "SOT-23; 3 Leads; Body 3.0 x 2.6 mm, inc. leads (LxW max)"
  rect 0.8x0.9 smd: 1(-0.95,-1) 2(0.95,-1) 3(0,1)
  silkscreen extent -1.53,-1.45 1.54,0.77
SOT-323-5 [mm] "SOT-323; 5 Leads; Body 2.2 x 2.2 mm, inc. leads (LxW max)"
  rect 0.4x0.5 smd: 1(-0.65,-0.95) 2(0,-0.95) 3(0.65,-0.95) 4(0.65,0.95) 5(-0.65,0.95)
  silkscreen extent -1.03,-1.2 1.03,0.65
SW_BFS [mm] "Omron BFS tactile switch (SMD)"
  rect 1.6x1.4 smd: 1(-4,-2.25) 1(4,-2.25) 2(-4,2.25) 2(4,2.25)
  silkscreen extent -3,-3.15 3,3.15, body extent -4,-3.15 4,3.15, height 3.1
TP-PTH-25/45 [mil] "Test point, plated through-hole, 25/45mil"
  round 45 hole 25: 1(0,0)
TP-SMD20 [mil] "Test point, surface-mount, 20mil"
  round 20 smd paste-78.74: 1(0,0)
TP_MED [mil] "Testpoint - medium sized"
  round 100 hole 65: 1(0,0)
TPS25940 [mm] "QFN, 20-Leads, Body 3x4mm, Pitch 0.5mm"
  rect 0.2x0.6 smd: 1(-1.25,-1.4) 2(-0.75,-1.4) 3(-0.25,-1.4) 4(0.25,-1.4) 5(0.75,-1.4) 6(1.25,-1.4) 11(1.25,1.4) 12(0.75,1.4) 13(0.25,1.4) 14(-0.25,1.4) 15(-0.75,1.4) 16(-1.25,1.4)
  rect 0.6x0.2 smd: 7(1.9,-0.75) 8(1.9,-0.25) 9(1.9,0.25) 10(1.9,0.75) 17(-1.9,0.75) 18(-1.9,0.25) 19(-1.9,-0.25) 20(-1.9,-0.75)
  rect 2.6x1.6 smd paste-3: PAD(0,0)
  silkscreen extent -2.38,-1.88 2,1.5, body extent -2,-1.5 2,1.5, height 0.8

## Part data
*1: library part OKLOGO
C1 C2 C3 C6 C7 C9: library part 000070, "Ceramic capacitor"
C4 C5: library part 001368, "Ceramic Capacitor"
C8 C10 C12 C18 C20: library part 000480, "Ceramic capacitor"
C11 C13 C19 C21: library part 000491, "Ceramic capacitor"
C14 C15 C22 C23: library part 001219, "Ceramic capacitor"
C16 C17 C24 C25: library part 000295, "Ceramic Capacitor"
D1 D3 D4: library part 000012, "LED"
D2: library part 000011, "LED"
FID1 FID2 FID3 FID4: "PCB fiducial"
J1: library part 001370, "SODIMM socket, DDR3, 204-pin, gold flash, 5.2mm height, surface-mount"
J2 J3: library part 001338, "2mm header, 10x2, thru-hole"
J4 J5 J6 J7: library part 000583, "2mm header, 20x2, thru-hole"
J8: library part 000777, "2.54mm, 10 Pos, Dual Row Header"
J9 J10 J11 J12: library part 000875, ".100 Female Receptacle"
J13: library part 000356, "DC power connector - high current"
Q1 Q2 Q3: library part 001237, "N-Channel, Logic Level, MOSFET"
R1 R4 R7 R9 R10 R12: library part 000755, "Thick-film resistor"
R2 R3 R5 R6 R8 R11 R16 R18 R19 R53 R65 R66 R67 R68 R69 R70 R71 R72 R73 R77 R78 R79 R80 R81 R82 R83 R84 R85: library part 000759, "Thick-film resistor"
R13 R14 R17 R52 R63 R64 R75 R76: library part 000411, "Zero-ohm resistor"
R15 R62 R74: library part 000827, "Thick-film resistor"
R20 R21 R22 R23 R24 R25 R26 R27 R28 R29 R30 R31 R32 R33 R34 R35 R36 R37 R38 R39 R40 R41 R42 R43 R44 R45 R46 R47 R48 R49 R50 R51: library part 000780, "Thick-film resistor"
R54 R61: library part 001332, "Thick-film resistor"
R55: library part 001070, "Thick-film resistor"
R56 R60: library part 000934, "Thick-film resistor"
R57: library part 000803, "Thick-film resistor"
R58: library part 001008, "Thick-film resistor"
R59: library part 001032, "Thick-film resistor"
S1 S2: library part 000010, "Pushbutton"
S3 S4: library part 000310, "Sealed, 8 SPST DIP switch"
TP1 TP2 TP3 TP4 TP5 TP6 TP7 TP8 TP9 TP10: library part 000265, "Testpoint"
TP11 TP12 TP13: "Test point, plated through-hole, 25/45mil"
TP14 TP15 TP16 TP17 TP18 TP19: "Test point, surface-mount, 20mil"
U1 U2 U3 U4 U5 U6 U7 U8: library part 000889, "TVS ARRAY - ESD Protection Diode"
U9: library part 001325, "18V eFuse with reverse- /over-voltage protection and current limiting, auto-retry"
U10 U11 U12 U13: library part 001209, "LDO voltage regulator"

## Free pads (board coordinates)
  round 275.59 hole 137.8: MH(0,0) MH(0,3346.46) MH(5314.96,0) MH(5314.96,3346.46)

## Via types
v1: diameter 16, hole 8, L1-TOP to L4-BOT, tented both sides, 406 vias

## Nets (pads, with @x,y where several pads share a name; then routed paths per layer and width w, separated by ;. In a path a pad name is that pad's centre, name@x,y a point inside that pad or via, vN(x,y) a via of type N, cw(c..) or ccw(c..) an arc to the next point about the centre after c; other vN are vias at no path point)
+2.5VDD: J1.9 J1.10 J2.1 R15.2 R16.2 R62.2 R65.2 R74.2 R77.2 TP10.1 | length 6507.1
  L1-TOP w10: R15.2@91.72,811 v1(119,811) ; R62.2@91.72,1067 v1(116,1067) ; R65.2@326,1045.72 349.28,1045.72 v1(350,1045) ; R16.2@328,790.09 328.28,790.37 v1(352,790.37) ; J1.9@1504.44,1335.92 1504.44,1284.56 v1(1505,1284) ; v1(1516,1711) v1@1516.25,1710.75
  L1-TOP w12: J1.10@1516.25,1658.76 v1@1516.25,1710.75
  L1-TOP w16: v1(352,790.37) 590.55,551.82 590.55,275.59 798.14,68 4278,68 4434,224 4809,224 4898,313 4898,524 5293,919 5293,976 5276.28,992.72 R77.2@5257,992.72 5258.5,994.22 5258.5,1051.5 5242,1068 5073.72,1068 R74.2@5021.72,1016
+VDC: C4.1 C5.1 C7.2 C8.2 C10.2 C12.2 C18.2 C20.2 J1.1 J1.2 J1.3 J1.4 J1.5 R52.2 R53.2 R54.2 S3.9 S4.9 TP1.1 TP12.1 U9.4 U9.5 U9.6 U9.7 U9.8 U10.15 U10.16 U10.17 U11.15 U11.16 U11.17 U12.15 U12.16 U12.17 U13.15 U13.16 U13.17 | length 731.3
  L1-TOP w6: R53.2@772.72,2578 803,2578 825,2600 825,2655 824,2656 ; R54.2@772.72,2656 824,2656 ; v1(885,2685) 885,2670 871,2656 824,2656
  L1-TOP w10: S3.9@549.5,1340 610,1340 v1(611,1339) ; J1.1@1409.95,1335.92 1409.95,1284.05 v1(1410,1284) ; J1.2@1421.76,1658.76 1421.76,1710.76 v1(1422,1711) ; J1.3@1433.57,1335.92 1433.57,1284.43 v1(1434,1284) ; J1.4@1445.39,1658.76 1445.39,1710.39 v1(1446,1711) ; v1(1457,1284) 1457.2,1284.2 J1.5@1457.2,1335.92 ; S4.9@5189.5,1340 5255,1340 v1@5256,1339
  L1-TOP w32: R52.2@1038,2692.54 1119.46,2692.54 TP12.1@1126,2686
  other v1: 5253,1339 992.18,1428.57 1004.18,1442.57 1004.18,1461.57 4341.36,1516.87 4341.36,1535.87 4353.36,1549.87 1006.18,1896.57 1018.18,1910.57 1018.18,1929.57 4340.36,1983.87 4340.36,2002.87 4352.36,2016.87 910,2685 935,2685 960,2685
+VDCIN: C6.2 J13.1 R52.1 R55.2 R57.2 TP11.1 U9.9 U9.10 U9.11 U9.12 U9.13 | length 1452.1
  L1-TOP w7: 451,2707.07 451,2403.28 R57.2@498.28,2356
  L1-TOP w10: 451,2707.07 465.65,2721.72 R55.2@487,2721.72
  L1-TOP w32: J13.1@342.37,2755 342.37,2851.37 413,2922 979,2922 1038,2863 R52.1@1038,2759.46 1120.72,2759.46 TP11.1@1126,2764.74
BANK2A_L9N: J1.14 J3.3 | length 2033
  L1-TOP w6: J3.3@729.92,3346.46 729.92,3300.08 1563.5,2466.5 J1.14@1563.5,1658.76
BANK2A_L9P: J1.12 J3.4 | length 2134.2
  L1-TOP w6: J3.4@729.92,3425.2 691,3386.28 691,3299 1539.87,2450.13 J1.12@1539.87,1658.76
BANK2A_L10N: J1.22 J3.7 | length 2006.9
  L1-TOP w6: J3.7@887.4,3346.46 887.4,3302.6 1657.98,2532.02 J1.22@1657.98,1658.76
BANK2A_L10P: J1.20 J3.8 | length 2107.7
  L1-TOP w6: J3.8@887.4,3425.2 849,3386.8 849,3301 1634.36,2515.64 J1.20@1634.36,1658.76
BANK2A_L11N: J1.18 J3.5 | length 2019.9
  L1-TOP w6: J3.5@808.66,3346.46 808.66,3301.34 1610.74,2499.26 J1.18@1610.74,1658.76
BANK2A_L11P: J1.16 J3.6 | length 2122.1
  L1-TOP w6: J3.6@808.66,3425.2 805.2,3425.2 771,3391 771,3299 1587.12,2482.88 J1.16@1587.12,1658.76
BANK2A_L12N: J1.26 J3.9 | length 1993.8
  L1-TOP w6: J3.9@966.14,3346.46 966.14,3303.86 1705.23,2564.77 J1.26@1705.23,1658.76
BANK2A_L12P: J1.24 J3.10 | length 2093.6
  L1-TOP w6: J3.10@966.14,3425.2 929,3388.06 929,3301 1681.61,2548.39 J1.24@1681.61,1658.76
BANK2A_L13N: J1.11 J2.4 R33.1 | length 1831.2
  L1-TOP w6: R33.1@1263,586.72 1249.72,600 840,600 691,749 691,827.22 J2.4@729.92,866.14 729.92,920.92 1073,1264 1514,1264 1528.06,1278.06 J1.11@1528.06,1335.92
BANK2A_L13P: J1.13 J2.3 R32.1 | length 1835.7
  L1-TOP w6: R32.1@1308,586.72 1308,607 1295,620 860,620 729.92,750.08 J2.3@729.92,787.4 729.92,797.92 770,838 770,926 1089,1245 1519,1245 1551.68,1277.69 J1.13@1551.68,1335.92
BANK2A_L14N: J1.15 J2.6 R29.1 | length 1832.5
  L1-TOP w6: R29.1@1353,586.72 1353,608 1321,640 880,640 766.01,753.99 766.01,810.01 808.66,852.66 J2.6@808.66,866.14 808.66,923.66 1111,1226 1532,1226 1575.31,1269.31 J1.15@1575.31,1335.92
BANK2A_L14P: J1.17 J2.5 R28.1 | length 1821.9
  L1-TOP w6: J2.5@808.66,787.4 808.66,751.34 900,660 1355,660 1398,617 R28.1@1398,586.72 ; J2.5@812,787.4 812,799 849,836 849,919 1136,1206 1539,1206 1598.93,1265.93 J1.17@1598.93,1335.92
BANK2A_L15N: J1.19 J2.8 R25.1 | length 1814
  L1-TOP w6: R25.1@1443,586.72 1443,607 1370,680 920,680 851.31,748.69 851.31,814.31 887.4,850.4 J2.8@887.4,866.14 887.4,926.4 1149,1188 1553,1188 1622.55,1257.55 J1.19@1622.55,1335.92
BANK2A_L15P: J1.21 J2.7 R24.1 | length 1804.3
  L1-TOP w6: R24.1@1488,586.72 1488,613 1401,700 940,700 887.4,752.6 J2.7@887.4,787.4 887.4,796.4 927,836 927,916 1180,1169 1559,1169 1646.17,1256.17 J1.21@1646.17,1335.92
BANK2A_L16N: J1.25 J2.9 R20.1 | length 1757
  L1-TOP w6: R20.1@1578,586.72 1578,607 1445,740 1013.54,740 J2.9@966.14,787.4 1006,827.26 1006,901 1235,1130 1577,1130 1693.42,1246.42 J1.25@1693.42,1335.92
BANK2A_L16P: J1.23 J2.10 R21.1 | length 1783.6
  L1-TOP w6: R21.1@1533,586.72 1533,607 1420,720 970,720 927,763 927,814 966.14,853.14 J2.10@966.14,866.14 966.14,908.14 1208,1150 1570,1150 1669.8,1249.8 J1.23@1669.8,1335.92
BANK3A_B1N_DATA6: J1.57 J4.7 R30.1 | length 1355.6
  L1-TOP w6: J1.57@2071.37,1335.92 2071.37,1164.37 1793,886 1793,840 1753.54,800.54 J4.7@1753.54,787.4 1753.54,734.46 1838,650 2262,650 2300,612 R30.1@2300,586.72
BANK3A_B1P_DATA8: J1.55 J4.8 R31.1 | length 1347.4
  L1-TOP w6: J1.55@2047.75,1335.92 2047.75,1189.75 1753.54,895.54 J4.8@1753.54,866.14 1753.54,851.54 1715,813 1715,741 1826,630 2230,630 2255,605 R31.1@2255,586.72
BANK3A_B2N_DATA5: J1.66 J5.10 | length 1942
  L1-TOP w6: J5.10@1832.28,3425.2 1793,3385.91 1793,3304 2177.67,2919.33 J1.66@2177.67,1658.76
BANK3A_B2P_DATA7: J1.68 J5.9 | length 1840.5
  L1-TOP w6: J5.9@1832.28,3346.46 1832.28,3301.72 2201.29,2932.71 J1.68@2201.29,1658.76
BANK3A_B3N_DATA10: J1.54 J5.1 | length 1902.5
  L1-TOP w6: J5.1@1517.32,3346.46 1517.32,3302.68 2035.94,2784.06 J1.54@2035.94,1658.76
BANK3A_B3P_DATA12: J1.52 J5.2 | length 2014
  L1-TOP w6: J5.2@1517.32,3425.2 1466,3373.87 1466,3306 2012.32,2759.69 J1.52@2012.32,1658.76
BANK3A_B4N_DATA9: J1.65 J4.12 R23.1 | length 1354.3
  L1-TOP w6: J1.65@2165.86,1335.92 2165.86,1164.86 1911.02,910.02 J4.12@1911.02,866.14 1911.02,853.02 1872,814 1872,751 1913,710 2340,710 2435,615 R23.1@2435,586.72
BANK3A_B4P_DATA11: J1.67 J4.11 R22.1 | length 1352.1
  L1-TOP w6: J1.67@2189.48,1335.92 2189.48,1160.48 1951,922 1951,827.38 J4.11@1911.02,787.4 1911.02,748.98 1938,722 2368,722 2480,610 R22.1@2480,586.72
BANK3A_B5N_DATA14: J1.59 J4.10 R27.1 | length 1349.2
  L1-TOP w6: J1.59@2094.99,1335.92 2094.99,1159.99 1832.28,897.28 J4.10@1832.28,866.14 1832.28,854.28 1792,814 1792,739 1861,670 2280,670 2345,605 R27.1@2345,586.72
BANK3A_B5P_CLKUSR: J1.61 J4.9 R26.1 | length 1347.8
  L1-TOP w6: J1.61@2118.61,1335.92 2118.61,1146.61 1871,899 1871,839 1832.28,800.28 J4.9@1832.28,787.4 1832.28,742.72 1885,690 2310,690 2390,610 R26.1@2390,586.72
BANK3A_B6N_DATA13: J1.62 J5.8 | length 1956.1
  L1-TOP w6: J5.8@1753.54,3425.2 1713,3384.65 1713,3294 2130.43,2876.57 J1.62@2130.43,1658.76
BANK3A_B6P_DATA15: J1.64 J5.7 | length 1853.6
  L1-TOP w6: J5.7@1753.54,3346.46 1753.54,3299.46 2154.05,2898.95 J1.64@2154.05,1658.76
BANK3A_B7N_PR_DONE: J1.51 J4.6 R35.1 | length 1344.9
  L1-TOP w6: J1.51@2000.5,1335.92 2000.5,1191.84 J4.6@1674.8,866.14 1674.8,855.71 1635,815.91 1635,733 1781.28,586.72 R35.1@2165,586.72
BANK3A_B7P_PR_ERROR: J1.53 J4.5 R34.1 | length 1347.6
  L1-TOP w6: J1.53@2024.13,1335.92 2024.13,1191.13 1716,883 1716,841 1674.8,799.8 J4.5@1674.8,787.4 1674.8,742.2 1807,610 2203,610 2210,603 R34.1@2210,586.72
BANK3A_B8N: J1.58 J5.5 | length 1856.9
  L1-TOP w6: J5.5@1674.8,3346.46 1674.8,3287.2 2083.18,2878.82 J1.58@2083.18,1658.76
BANK3A_B8P: J1.56 J5.6 | length 1957.1
  L1-TOP w6: J5.6@1674.8,3425.2 1637,3387.39 1637,3289 2059.56,2866.44 J1.56@2059.56,1658.76
BANK3B_B9N: J1.75 J4.15 | length 676.9
  L1-TOP w6: J4.15@2068.5,787.4 2108,826.9 2108,893 2378.46,1163.46 J1.75@2378.46,1335.92
BANK3B_B9P: J1.73 J4.16 | length 588.4
  L1-TOP w6: J4.16@2068.5,866.14 2068.5,908.5 2354.83,1194.83 J1.73@2354.83,1335.92
BANK3B_B10N: J1.76 J5.14 | length 1964.4
  L1-TOP w6: J5.14@1989.76,3425.2 1951,3386.43 1951,3314 2390.27,2874.73 J1.76@2390.27,1658.76
BANK3B_B10P: J1.78 J5.13 | length 1863.4
  L1-TOP w6: J5.13@1989.76,3346.46 1989.76,3312.24 2413.89,2888.11 J1.78@2413.89,1658.76
BANK3B_B11N: J1.69 J4.14 | length 562.3
  L1-TOP w6: J4.14@1989.76,866.14 1989.76,931.76 2213.1,1155.1 J1.69@2213.1,1335.92
BANK3B_B11P: J1.71 J4.13 | length 650.8
  L1-TOP w6: J4.13@1989.76,787.4 2031,828.64 2031,941 2236.72,1146.72 J1.71@2236.72,1335.92
BANK3B_B12N: J1.79 J4.18 | length 585.1
  L1-TOP w6: J4.18@2147.24,866.14 2147.24,902.24 2425.7,1180.7 J1.79@2425.7,1335.92
BANK3B_B12P: J1.81 J4.17 | length 673.6
  L1-TOP w6: J4.17@2147.24,787.4 2186,826.16 2186,921 2449.32,1184.32 J1.81@2449.32,1335.92
BANK3B_B13N: J1.83 J4.20 | length 572.1
  L1-TOP w6: J4.20@2225.98,866.14 2225.98,916.98 2472.94,1163.94 J1.83@2472.94,1335.92
BANK3B_B13P: J1.85 J4.19 | length 660.6
  L1-TOP w6: J4.19@2225.98,787.4 2225.98,802.98 2266,843 2266,922 2496.57,1152.57 J1.85@2496.57,1335.92
BANK3B_B14N: J1.70 J5.12 | length 1927.1
  L1-TOP w6: J5.12@1911.02,3425.2 1874,3388.17 1874,3319 2224.91,2968.09 J1.70@2224.91,1658.76
BANK3B_B14P: J1.72 J5.11 | length 1827.5
  L1-TOP w6: J5.11@1911.02,3346.46 1911.02,3315.98 2248.54,2978.46 J1.72@2248.54,1658.76
BANK3B_B15N_CLK0N: J1.94 J5.22 | length 1922.8
  L1-TOP w6: J5.22@2304.72,3425.2 2265,3385.47 2265,3280 2602.87,2942.13 J1.94@2602.87,1658.76
BANK3B_B15P_CLK0P: J1.96 J5.21 | length 1821
  L1-TOP w6: J5.21@2304.72,3346.46 2304.72,3299.28 2626.49,2977.51 J1.96@2626.49,1658.76
BANK3B_B16N: J1.95 J4.25 R46.1 | length 1462.3
  L1-TOP w5.5: J4.25@2462.2,787.4 2462.2,757.8 2560,660 3150,660 3197,613 R46.1@3197,586.72
  L1-TOP w6: J4.25@2462.2,787.4 2462.2,799.2 2503,840 2503,928 2614.68,1039.68 J1.95@2614.68,1335.92
BANK3B_B16P: J1.93 J4.26 R47.1 | length 1457.4
  L1-TOP w5.5: J4.26@2462.2,866.14 2462.2,853.2 2424,815 2424,766 2550,640 3126,640 3152,614 R47.1@3152,586.72
  L1-TOP w6: J4.26@2462.2,866.14 2462.2,918.2 2591.06,1047.06 J1.93@2591.06,1335.92
BANK3B_B17N: J1.89 J4.21 R50.1 | length 1546
  L1-TOP w5.5: J4.21@2304.72,787.4 2342.38,749.75 2410.25,749.75 2540,620 3096,620 3107,609 R50.1@3107,586.72
  L1-TOP w6: J4.21@2304.72,787.4 2344,826.68 2344,930 2543.81,1129.81 J1.89@2543.81,1335.92
BANK3B_B17P: J1.87 J4.22 R51.1 | length 1547.2
  L1-TOP w6: J1.87@2520.19,1335.92 2520.19,1147.19 2304.72,931.72 J4.22@2304.72,866.14 2304.72,854.72 2266,816 2266,763 2293,736 2394,736 2530,600 3048.72,600 R51.1@3062,586.72
BANK3B_B18N: J1.92 J5.19 | length 1834
  L1-TOP w6: J5.19@2225.98,3346.46 2225.98,3289.02 2579.24,2935.76 J1.92@2579.24,1658.76
BANK3B_B18P: J1.90 J5.20 | length 1935.3
  L1-TOP w6: J5.20@2225.98,3425.2 2187,3386.21 2187,3289 2555.62,2920.38 J1.90@2555.62,1658.76
BANK3B_B19N: J1.104 J5.28 | length 1872.4
  L1-TOP w6: J5.28@2540.94,3425.2 2503,3387.25 2503,3286 2720.98,3068.02 J1.104@2720.98,1658.76
BANK3B_B19P: J1.106 J5.27 | length 1772.1
  L1-TOP w6: J5.27@2540.94,3346.46 2540.94,3283.06 2744.6,3079.4 J1.106@2744.6,1658.76
BANK3B_B20N: J1.100 J5.25 | length 1775.3
  L1-TOP w6: J5.25@2462.2,3346.46 2462.2,3284.8 2673.73,3073.27 J1.100@2673.73,1658.76
BANK3B_B20P: J1.98 J5.26 | length 1875.9
  L1-TOP w6: J5.26@2462.2,3425.2 2424,3386.99 2424,3257 2650.11,3030.89 J1.98@2650.11,1658.76
BANK3B_B21N_BL_CLKOUTN: J1.97 J4.28 R43.1 | length 1454.9
  L1-TOP w5.5: J4.28@2540.94,866.14 2540.94,855.94 2502,817 2502,758 2580,680 3165,680 3242,603 R43.1@3242,586.72
  L1-TOP w6: J4.28@2540.94,866.14 2540.94,933.94 2638.3,1031.3 J1.97@2638.3,1335.92
BANK3B_B21P_BL_CLKOUTP: J1.99 J4.27 R42.1 | length 1456.3
  L1-TOP w5.5: J4.27@2540.94,787.4 2540.94,759.06 2600,700 3194,700 3287,607 R42.1@3287,586.72
  L1-TOP w6: J4.27@2540.94,787.4 2540.94,798.94 2579,837 2579,941 2661.92,1023.92 J1.99@2661.92,1335.92
BANK3B_B22N: J1.84 J5.18 | length 1937.1
  L1-TOP w6: J5.18@2147.24,3425.2 2110,3387.95 2110,3296 2484.76,2921.24 J1.84@2484.76,1658.76
BANK3B_B22P: J1.86 J5.17 | length 1837.3
  L1-TOP w6: J5.17@2147.24,3346.46 2147.24,3302.76 2508.38,2941.62 J1.86@2508.38,1658.76
BANK3B_B23N: J1.80 J5.16 | length 1952
  L1-TOP w6: J5.16@2068.5,3425.2 2029,3385.69 2029,3311 2437.51,2902.49 J1.80@2437.51,1658.76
